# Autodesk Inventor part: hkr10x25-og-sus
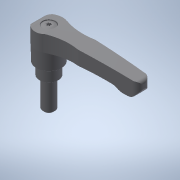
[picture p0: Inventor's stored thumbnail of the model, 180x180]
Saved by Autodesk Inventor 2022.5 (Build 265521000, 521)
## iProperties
Created: 2017-09
Part Number: hkr10x25-og-sus
Material: 一般
Document SubType Name: Modeling
Designer: imaocorp
Density: 1 g/cm^3
Appearance: 既定
Author: imaocorp
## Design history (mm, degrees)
node "hkr10x25-og-sus.x_t1"
node "hkr10x25-og-sus"
node "Base1"
